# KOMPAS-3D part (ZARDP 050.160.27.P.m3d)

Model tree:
1. Булева операция:1
2. Булева операция:2
3. Булева операция:3
4. Булева операция:4
5. Булева операция:5
6. Булева операция:6
7. Булева операция:7
8. Булева операция:8
9. Булева операция:9
10. Булева операция:10
11. Булева операция:11
12. Булева операция:12
13. Булева операция:13
14. Булева операция:14
15. Булева операция:15
16. Булева операция:16
17. Булева операция:17
18. Булева операция:18
19. Булева операция:19
20. Булева операция:20
21. Булева операция:21
22. Булева операция:22
23. Булева операция:23
24. Булева операция:24
25. Булева операция:25
26. Булева операция:26

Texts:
  ООО ИК Энерпред-Ярдос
